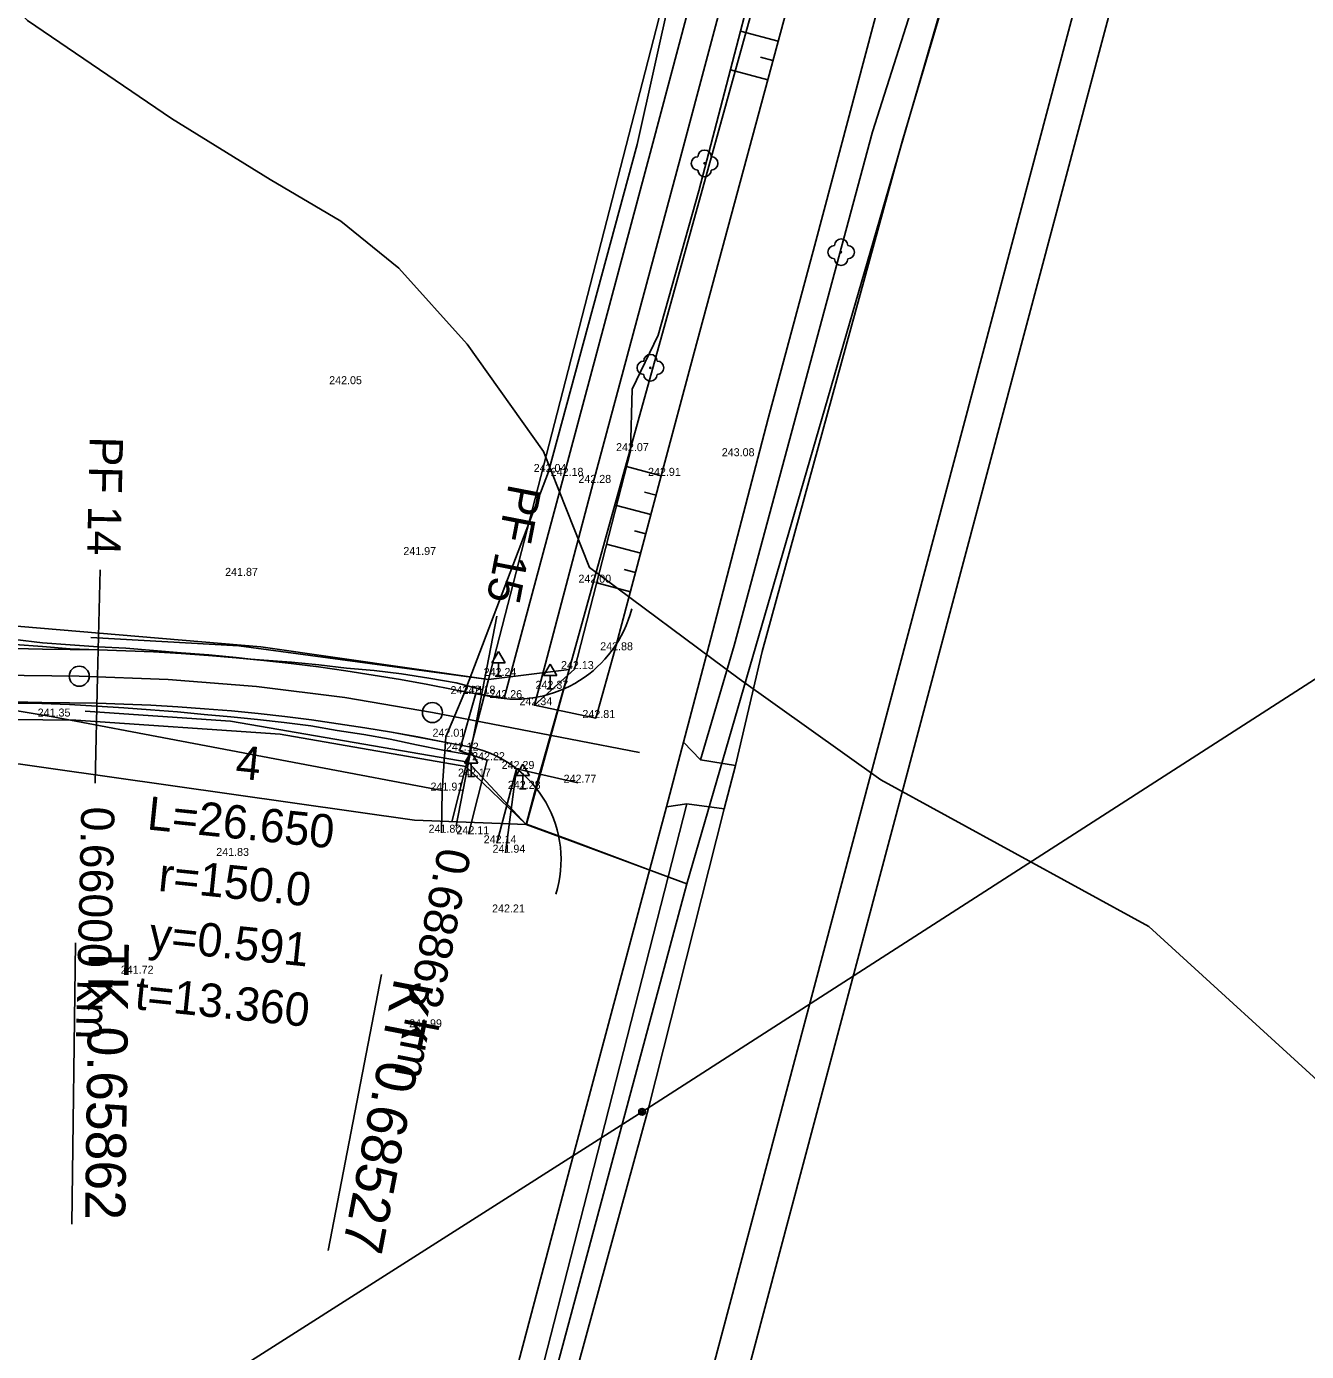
# Model space of a CAD drawing. Extents: x -555887 to -552101, y -1100251 to -1096546.
# Drawn here: x -554028.8 to -553932.8, y -1098461.3 to -1098361.9 of the extents above; entities that cross this region are included whole.
import ezdxf

# ---------------------------------------------------------------- set-up
doc = ezdxf.new("R2010")
doc.units = 0
for name, color, linetype in [('07_ELEKTRO', 7, 'Continuous'), ('07_KANALIZACE', 7, 'Continuous'), ('07_VODOVOD', 7, 'Continuous'), ('PARCELY_cesty', 7, 'Continuous'), ('PARCELY_silnice', 7, 'Continuous'), ('POLYGONY_rozšíření', 7, 'Continuous'), ('POLYGONY_SITUACE_PF', 7, 'Continuous'), ('POLYGONY_SITUACE_PF_POPISY', 7, 'Continuous'), ('POLYGONY_SITUACE_PO', 7, 'Continuous'), ('ROZHLED_parcela_cesty', 7, 'Continuous'), ('vrstevnice', 7, 'Continuous'), ('Výškopis', 7, 'Continuous'), ('ZSST', 7, 'Continuous'), ('zájem', 7, 'Continuous')]:
    doc.layers.add(name, color=color, linetype=linetype)

msp = doc.modelspace()

# ---------------------------------------------------------------- linework, layer by layer
for p, q in [((-554025.076, -1098430.632), (-554025.365, -1098451.722)), ((-554002.13, -1098432.993), (-554006.142, -1098453.7))]:
    msp.add_line(p, q)
at = {"layer": '07_ELEKTRO'}
msp.add_line((-554067.43, -1098497.29), (-553982.61, -1098443.29), dxfattribs=at)
msp.add_lwpolyline([(-553982.61, -1098443.29), (-553898.74, -1098389.37), (-553814.74, -1098335.79), (-553822.57, -1098304.65)], dxfattribs=at)
at = {"layer": '07_KANALIZACE'}
msp.add_lwpolyline([(-554087.209, -1098884.94), (-554044.091, -1098723.546), (-553946.28, -1098356.13), (-553945.28, -1098350.61), (-553945.106, -1098348.205), (-553937.04, -1098317.66), (-553932.95, -1098309.77), (-553933.89, -1098299.13), (-553960.89, -1098094.71)], dxfattribs=at)
at = {"layer": '07_VODOVOD'}
msp.add_lwpolyline([(-554079.661, -1098847.144), (-553997.696, -1098539.175), (-553945.85, -1098344.3), (-553938.248, -1098317.523), (-553935.78, -1098308.01), (-553936.175, -1098296.386), (-554003.21, -1097797.26)], dxfattribs=at)
at = {"layer": 'PARCELY_cesty'}
for points in [[(-554666.58, -1098424.3), (-554661.613, -1098426.35), (-554474.619, -1098365.555), (-554470.001, -1098364.247), (-554462.918, -1098362.998), (-554455.97, -1098362.75), (-554451.048, -1098362.623), (-554296.95, -1098373.16), (-554290.885, -1098371.599), (-554270.388, -1098373.304), (-554264.04, -1098376.17), (-554253.344, -1098377.565), (-554081.032, -1098403.398), (-554065.658, -1098405.306), (-554039.82, -1098406.01), (-554011.196, -1098408.42), (-553994.13, -1098410.89)], [(-553996.876, -1098421.543), (-553995.81, -1098417.41), (-553994.13, -1098410.89)], [(-554054.66, -1098413.62), (-554025.06, -1098413.92), (-554009.73, -1098414.99), (-553995.81, -1098417.41), (-553991.3, -1098421.75)]]:
    msp.add_lwpolyline(points, dxfattribs=at)
at = {"layer": 'PARCELY_silnice'}
for points in [[(-553977.83, -1098347.65), (-553971.09, -1098348.95), (-553988.06, -1098410.12), (-553994.13, -1098410.89)], [(-553988.06, -1098410.12), (-553991.282, -1098421.727), (-553987.992, -1098422.937), (-553982.15, -1098425.12), (-553979.24, -1098426.19), (-553957.61, -1098351.63), (-553971.09, -1098348.95)]]:
    msp.add_lwpolyline(points, close=True, dxfattribs=at)
at = {"layer": 'POLYGONY_rozšíření'}
for centre, radius, start, end in [((-553992.106, -1098403.347), 9.007, 259.0322, 345.60865), ((-553997.328, -1098424.393), 8.648, 342.61563, 77.16163)]:
    msp.add_arc(centre, radius, start, end, dxfattribs=at)
at = {"layer": 'POLYGONY_SITUACE_PF'}
for p, q in [((-554023.24, -1098402.661), (-554023.423, -1098410.659)), ((-553993.504, -1098406.144), (-553995.026, -1098413.998)), ((-554023.423, -1098410.659), (-554023.606, -1098418.657)), ((-553995.026, -1098413.998), (-553996.547, -1098421.852))]:
    msp.add_line(p, q, dxfattribs=at)
at = {"layer": 'POLYGONY_SITUACE_PO'}
for p, q in [((-554029.645, -1098408.567), (-554027.561, -1098408.595)), ((-554029.64, -1098408.25), (-554027.559, -1098408.414)), ((-554029.635, -1098407.883), (-554027.555, -1098408.122)), ((-554027.561, -1098408.595), (-554025.478, -1098408.624)), ((-554027.559, -1098408.414), (-554025.478, -1098408.578)), ((-554027.555, -1098408.122), (-554025.474, -1098408.274)), ((-554025.478, -1098408.578), (-554023.377, -1098408.659)), ((-554025.478, -1098408.624), (-554023.377, -1098408.659)), ((-554025.474, -1098408.274), (-554023.372, -1098408.436)), ((-554023.377, -1098408.659), (-554021.306, -1098408.727)), ((-554023.377, -1098408.659), (-554021.306, -1098408.727)), ((-554023.372, -1098408.436), (-554021.299, -1098408.537)), ((-554021.306, -1098408.727), (-554019.235, -1098408.813)), ((-554021.306, -1098408.727), (-554019.235, -1098408.813)), ((-554021.299, -1098408.537), (-554019.229, -1098408.699)), ((-554019.235, -1098408.813), (-554017.166, -1098408.929)), ((-554019.235, -1098408.813), (-554017.166, -1098408.929)), ((-554019.229, -1098408.699), (-554017.163, -1098408.884)), ((-554017.166, -1098408.929), (-554015.099, -1098409.082)), ((-554017.166, -1098408.929), (-554015.099, -1098409.082)), ((-554017.163, -1098408.884), (-554015.096, -1098409.039)), ((-554015.099, -1098409.082), (-554013.034, -1098409.252)), ((-554015.099, -1098409.082), (-554013.034, -1098409.252)), ((-554015.096, -1098409.039), (-554013.031, -1098409.219)), ((-554013.034, -1098409.252), (-554010.971, -1098409.457)), ((-554013.034, -1098409.252), (-554010.971, -1098409.457)), ((-554013.031, -1098409.219), (-554011.938, -1098409.361)), ((-554011.938, -1098409.361), (-554010.968, -1098409.428)), ((-554010.971, -1098409.457), (-554008.912, -1098409.686)), ((-554010.971, -1098409.457), (-554008.912, -1098409.686)), ((-554010.968, -1098409.428), (-554008.899, -1098409.582)), ((-554008.912, -1098409.686), (-554006.855, -1098409.94)), ((-554008.912, -1098409.686), (-554006.855, -1098409.94)), ((-554008.899, -1098409.582), (-554006.835, -1098409.791)), ((-554006.835, -1098409.791), (-554004.774, -1098410.034)), ((-554040.169, -1098410.423), (-554024.801, -1098410.634)), ((-554024.801, -1098410.634), (-554018.144, -1098410.873)), ((-554006.855, -1098409.94), (-554004.803, -1098410.235)), ((-554006.855, -1098409.94), (-554004.803, -1098410.235)), ((-554004.803, -1098410.235), (-554002.754, -1098410.546)), ((-554004.803, -1098410.235), (-554002.754, -1098410.546)), ((-554004.774, -1098410.034), (-554002.701, -1098410.216)), ((-554002.754, -1098410.546), (-554000.71, -1098410.883)), ((-554002.754, -1098410.546), (-554000.71, -1098410.883)), ((-554002.701, -1098410.216), (-554000.636, -1098410.46)), ((-554000.636, -1098410.46), (-553998.583, -1098410.792)), ((-553998.583, -1098410.792), (-553996.551, -1098411.119)), ((-554018.144, -1098410.873), (-554011.503, -1098411.407)), ((-554011.503, -1098411.407), (-554004.893, -1098412.236)), ((-554000.71, -1098410.883), (-553998.672, -1098411.26)), ((-554000.71, -1098410.883), (-553998.672, -1098411.26)), ((-553998.672, -1098411.26), (-553996.653, -1098411.645)), ((-553998.672, -1098411.26), (-553996.653, -1098411.645)), ((-553996.653, -1098411.645), (-553994.645, -1098412.034)), ((-553996.653, -1098411.645), (-553993.82, -1098412.19)), ((-553996.551, -1098411.119), (-553994.574, -1098411.665)), ((-554029.701, -1098412.649), (-554027.618, -1098412.68)), ((-554029.699, -1098412.567), (-554027.616, -1098412.595)), ((-554029.699, -1098412.567), (-554027.616, -1098412.595)), ((-554027.618, -1098412.68), (-554025.535, -1098412.751)), ((-554027.616, -1098412.595), (-554025.533, -1098412.624)), ((-554027.616, -1098412.595), (-554025.533, -1098412.624)), ((-554025.535, -1098412.751), (-554023.474, -1098412.878)), ((-554025.533, -1098412.624), (-554023.469, -1098412.658)), ((-554025.533, -1098412.624), (-554023.469, -1098412.658)), ((-554023.469, -1098412.658), (-554021.452, -1098412.724)), ((-554023.469, -1098412.658), (-554021.452, -1098412.724)), ((-554021.452, -1098412.724), (-554019.436, -1098412.808)), ((-554021.452, -1098412.724), (-554019.436, -1098412.808)), ((-554019.436, -1098412.808), (-554017.421, -1098412.921)), ((-554019.436, -1098412.808), (-554017.421, -1098412.921)), ((-554004.893, -1098412.236), (-553998.326, -1098413.358)), ((-554023.474, -1098412.878), (-554021.462, -1098413.003)), ((-554021.462, -1098413.003), (-554019.453, -1098413.16)), ((-554019.453, -1098413.16), (-554017.445, -1098413.302)), ((-554017.445, -1098413.302), (-554015.441, -1098413.494)), ((-554017.421, -1098412.921), (-554015.408, -1098413.07)), ((-554017.421, -1098412.921), (-554015.408, -1098413.07)), ((-554015.441, -1098413.494), (-554013.438, -1098413.676)), ((-554015.408, -1098413.07), (-554013.397, -1098413.235)), ((-554015.408, -1098413.07), (-554013.397, -1098413.235)), ((-554013.438, -1098413.676), (-554011.437, -1098413.885)), ((-554013.397, -1098413.235), (-554011.389, -1098413.435)), ((-554013.397, -1098413.235), (-554011.389, -1098413.435)), ((-554011.389, -1098413.435), (-554009.384, -1098413.658)), ((-554011.389, -1098413.435), (-554009.384, -1098413.658)), ((-554009.384, -1098413.658), (-554007.381, -1098413.905)), ((-554009.384, -1098413.658), (-554007.381, -1098413.905)), ((-553998.326, -1098413.358), (-553982.81, -1098416.364)), ((-554011.437, -1098413.885), (-554009.438, -1098414.111)), ((-554009.438, -1098414.111), (-554007.441, -1098414.354)), ((-554007.441, -1098414.354), (-554005.457, -1098414.695)), ((-554007.381, -1098413.905), (-554005.384, -1098414.193)), ((-554007.381, -1098413.905), (-554005.384, -1098414.193)), ((-554005.457, -1098414.695), (-554003.469, -1098414.998)), ((-554005.384, -1098414.193), (-554003.389, -1098414.495)), ((-554005.384, -1098414.193), (-554003.389, -1098414.495)), ((-554003.389, -1098414.495), (-554001.398, -1098414.824)), ((-554003.389, -1098414.495), (-554001.398, -1098414.824)), ((-554001.398, -1098414.824), (-553999.413, -1098415.19)), ((-554001.398, -1098414.824), (-553995.406, -1098415.962)), ((-554003.469, -1098414.998), (-554001.491, -1098415.36)), ((-554001.491, -1098415.36), (-553999.525, -1098415.783)), ((-553999.525, -1098415.783), (-553997.53, -1098416.17)), ((-553999.413, -1098415.19), (-553997.414, -1098415.572)), ((-553997.414, -1098415.572), (-553995.406, -1098415.961)), ((-553997.53, -1098416.17), (-553995.515, -1098416.521))]:
    msp.add_line(p, q, dxfattribs=at)
for centre in [(-554024.801, -1098410.634), (-553998.326, -1098413.358)]:
    msp.add_circle(centre, 0.75, dxfattribs=at)
at = {"layer": 'ROZHLED_parcela_cesty'}
msp.add_lwpolyline([(-554024.36, -1098413.26), (-554013.45, -1098414.01), (-553995.64, -1098417.08), (-553991.3, -1098421.75), (-553990.41, -1098418.43), (-553988.66, -1098412.24), (-553988.06, -1098410.12), (-553994.13, -1098410.89), (-554012.84, -1098408.35), (-554023.94, -1098407.74)], dxfattribs=at)
at = {"layer": 'vrstevnice'}
msp.add_lwpolyline([(-554031.026, -1098298.897), (-554035.452, -1098307.125), (-554039.309, -1098315.099), (-554043.291, -1098327.541), (-554043.87, -1098338.123), (-554041.542, -1098346.28), (-554037.622, -1098352.542), (-554028.673, -1098361.478), (-554017.894, -1098368.808), (-554010.495, -1098373.386), (-554005.187, -1098376.518), (-554000.845, -1098380.051), (-553995.729, -1098385.745), (-553989.99, -1098393.779), (-553986.558, -1098402.488), (-553975.316, -1098410.837), (-553964.711, -1098418.402), (-553944.61, -1098429.395), (-553930.532, -1098442.245)], dxfattribs=at)
at = {"layer": 'ZSST'}
for p, q in [((-553965.33, -1098369.81), (-553958.85, -1098349.53)), ((-553972.403, -1098363.022), (-553975.218, -1098362.264)), ((-553972.793, -1098364.47), (-553973.727, -1098364.219)), ((-553973.183, -1098365.919), (-553975.974, -1098365.167)), ((-553981.17, -1098395.61), (-553983.768, -1098394.921)), ((-553981.555, -1098397.06), (-553982.416, -1098396.831)), ((-553981.939, -1098398.51), (-553984.515, -1098397.826)), ((-553982.324, -1098399.96), (-553983.178, -1098399.733)), ((-553982.709, -1098401.409), (-553985.262, -1098400.732)), ((-553983.093, -1098402.859), (-553983.94, -1098402.635)), ((-553983.478, -1098404.309), (-553986.009, -1098403.638)), ((-553993.87, -1098409.62), (-553993.37, -1098408.77)), ((-553993.37, -1098408.77), (-553992.87, -1098409.62)), ((-553993.87, -1098409.62), (-553992.87, -1098409.62)), ((-553993.37, -1098410.62), (-553993.37, -1098409.62)), ((-553989.99, -1098410.58), (-553989.49, -1098409.73)), ((-553989.49, -1098409.73), (-553988.99, -1098410.58)), ((-553993.62, -1098410.62), (-553993.12, -1098410.62)), ((-553989.99, -1098410.58), (-553988.99, -1098410.58)), ((-553989.49, -1098411.58), (-553989.49, -1098410.58)), ((-553989.74, -1098411.58), (-553989.24, -1098411.58)), ((-553996.3, -1098416.22), (-553995.06, -1098411.94)), ((-553995.93, -1098417.16), (-553995.43, -1098416.31)), ((-553995.43, -1098416.31), (-553994.93, -1098417.16)), ((-553995.93, -1098417.16), (-553994.93, -1098417.16)), ((-553995.43, -1098418.16), (-553995.43, -1098417.16)), ((-553992.85, -1098423.87), (-553992.02, -1098417.59)), ((-553992.05, -1098418.08), (-553991.55, -1098417.23)), ((-553991.55, -1098417.23), (-553991.05, -1098418.08)), ((-553995.68, -1098418.16), (-553995.18, -1098418.16)), ((-553992.05, -1098418.08), (-553991.05, -1098418.08)), ((-553991.55, -1098419.08), (-553991.55, -1098418.08)), ((-553991.8, -1098419.08), (-553991.3, -1098419.08))]:
    msp.add_line(p, q, dxfattribs=at)
for points in [[(-553981.91, -1098371.05), (-553975.78, -1098348), (-553971.03, -1098329.61), (-553969.94, -1098324.32), (-553971.94, -1098323.51), (-553971.44, -1098318.93), (-553969.06, -1098318.21), (-553968.22, -1098303.02), (-553968.41, -1098291.14), (-553970.99, -1098268.85), (-553973.86, -1098246.72), (-553977.39, -1098220.02), (-553982.05, -1098183.91), (-553985.32, -1098159.26), (-553988.25, -1098137.18)], [(-553982.61, -1098443.29), (-553898.74, -1098389.37), (-553814.74, -1098335.79), (-553822.57, -1098304.65)], [(-553997.63, -1098422.37), (-553997.6, -1098419.21), (-554026.91, -1098413.66), (-554080.54, -1098404.72), (-554146.56, -1098393), (-554145.83, -1098373.42), (-554147.56, -1098338.87), (-554148.86, -1098314.99)], [(-554148.86, -1098314.99), (-554114.15, -1098321.64), (-554085.61, -1098327.06), (-554061.07, -1098330.97), (-554040.28, -1098335.39), (-554018.66, -1098339.2), (-553990.69, -1098343.82), (-553977.83, -1098347.63), (-553982.98, -1098370.76), (-553989.63, -1098395.32), (-553995.97, -1098411.98), (-553997.32, -1098415.17), (-553997.6, -1098419.21)], [(-553948.1, -1098341.33), (-553953.3, -1098345.41), (-553957.62, -1098352.08), (-553963.11, -1098370.53), (-553973.59, -1098408.79), (-553975.59, -1098417.34)], [(-554054.81, -1098696.59), (-554053.95, -1098693.56), (-554052.78, -1098689.01), (-554042.99, -1098652.55), (-554033.29, -1098616.71), (-554022.44, -1098576.81), (-554007.03, -1098518.73), (-553997.47, -1098483.19), (-553987.92, -1098447.16), (-553980.78, -1098420.44), (-553979.49, -1098415.59), (-553977.44, -1098407.81), (-553973.16, -1098391.31), (-553969.69, -1098378.4), (-553965.21, -1098361.58), (-553960.59, -1098344.24)], [(-553986.08, -1098413.77), (-553990.68, -1098412.81), (-553986.26, -1098396.14), (-553979.73, -1098371.75), (-553973.54, -1098348.54)], [(-553990.68, -1098412.81), (-553987.67, -1098410.1), (-553983.47, -1098393.76), (-553983.35, -1098389.1), (-553981.39, -1098385.06), (-553978.34, -1098374.25), (-553971.82, -1098349.22)], [(-553970.63, -1098356.44), (-553978.69, -1098386.36), (-553981.17, -1098395.61), (-553984.64, -1098408.69), (-553986.08, -1098413.77)], [(-553978.22, -1098416.9), (-553975.7, -1098408.34), (-553965.33, -1098369.81)], [(-553981.91, -1098371.05), (-553988.46, -1098395.61), (-553992.94, -1098412.28), (-553995.06, -1098411.94)], [(-553979.49, -1098415.59), (-553978.22, -1098416.9), (-553975.59, -1098417.34), (-553976.46, -1098420.59), (-553979.26, -1098420.2), (-553980.78, -1098420.44)], [(-553996.3, -1098416.22), (-553994.21, -1098416.93), (-553995.63, -1098422.48)], [(-553993.49, -1098423.16), (-553992.02, -1098417.59), (-553987.42, -1098418.62)], [(-554049.19, -1098691), (-554050.52, -1098687.46), (-554041.41, -1098653.36), (-554031.87, -1098617.14), (-554021.28, -1098577.24), (-554005.55, -1098519.29), (-553995.62, -1098484.1), (-553986.23, -1098447.46), (-553979.26, -1098420.2)], [(-553976.46, -1098420.59), (-553982.14, -1098443.13), (-553993.59, -1098484.91), (-554003.65, -1098520), (-554019.29, -1098577.95), (-554030.05, -1098617.61), (-554040, -1098653.89), (-554048.29, -1098689.04)]]:
    msp.add_lwpolyline(points, dxfattribs=at)
for centre, radius in [((-553977.92, -1098372.18), 0.05), ((-553967.68, -1098378.84), 0.05), ((-553981.98, -1098387.51), 0.05), ((-553982.61, -1098443.29), 0.25), ((-553982.61, -1098443.29), 0.158), ((-553982.61, -1098443.29), 0.05)]:
    msp.add_circle(centre, radius, dxfattribs=at)
for centre, start, end in [((-553978.42, -1098372.18), 90, 270), ((-553977.92, -1098371.68), 0, 180), ((-553977.42, -1098372.18), 270, 90), ((-553977.92, -1098372.68), 180, 0), ((-553967.68, -1098378.34), 0, 180), ((-553968.18, -1098378.84), 90, 270), ((-553967.18, -1098378.84), 270, 90), ((-553967.68, -1098379.34), 180, 0), ((-553982.48, -1098387.51), 90, 270), ((-553981.98, -1098387.01), 0, 180), ((-553981.48, -1098387.51), 270, 90), ((-553981.98, -1098388.01), 180, 0)]:
    msp.add_arc(centre, 0.5, start, end, dxfattribs=at)
at = {"layer": 'zájem'}
for points in [[(-554271.92, -1098380.9), (-554131.79, -1098402.65), (-553999.67, -1098421.44), (-553991.3, -1098421.75), (-553988.01, -1098422.96), (-553982.15, -1098425.12), (-553979.24, -1098426.19), (-554050.69, -1098691.93)], [(-554050.69, -1098691.93), (-553979.24, -1098426.19), (-553982.15, -1098425.12), (-553988.01, -1098422.96), (-553991.3, -1098421.75), (-553999.67, -1098421.44), (-554131.79, -1098402.65), (-554271.92, -1098380.9)]]:
    msp.add_lwpolyline(points, dxfattribs=at)

# ---------------------------------------------------------------- texts
for s, height, rotation, p in [('4', 2.5, 354.12426, (-554013.157, -1098418.274)), ('L=26.650', 2.5, 354.12426, (-554019.777, -1098422.117)), ('r=150.0', 2.5, 354.12426, (-554018.937, -1098426.727)), ('y=0.591', 2.5, 354.12426, (-554019.647, -1098431.178)), ('TK 0.65862', 3, 269.21411, (-554024.076, -1098430.645)), ('t=13.360', 2.5, 354.12426, (-554020.7, -1098435.593)), ('KT 0.68527', 3, 259.03441, (-554001.148, -1098433.183))]:
    msp.add_text(s, height=height, rotation=rotation).set_placement(p)
at = {"layer": 'POLYGONY_SITUACE_PF_POPISY'}
for s, rotation, p in [('PF 14', 268.68747, (-554024.01, -1098392.641)), ('PF 15', 259.03441, (-553992.583, -1098396.136)), ('0.66000 km', 268.68747, (-554024.646, -1098420.386)), ('0.68863 km', 259.03441, (-553997.863, -1098423.382))]:
    msp.add_text(s, height=2.5, rotation=rotation, dxfattribs=at).set_placement(p)
at = {"layer": 'Výškopis'}
for s, p in [('242.05', (-554006.062, -1098388.74)), ('242.07', (-553984.556, -1098393.76)), ('243.08', (-553976.628, -1098394.14)), ('242.04', (-553990.728, -1098395.32)), ('242.18', (-553989.454, -1098395.61)), ('242.28', (-553987.378, -1098396.14)), ('242.91', (-553982.158, -1098395.61)), ('241.97', (-554000.505, -1098401.55)), ('241.87', (-554013.862, -1098403.11)), ('242.00', (-553987.376, -1098403.62)), ('242.88', (-553985.744, -1098408.69)), ('242.13', (-553988.684, -1098410.1)), ('242.24', (-553994.482, -1098410.62)), ('242.01', (-553996.966, -1098411.98)), ('242.18', (-553996.054, -1098411.94)), ('242.26', (-553994.052, -1098412.28)), ('242.37', (-553990.594, -1098411.58)), ('242.34', (-553991.796, -1098412.81)), ('241.35', (-554027.916, -1098413.66)), ('242.81', (-553987.076, -1098413.77)), ('242.01', (-553998.316, -1098415.17)), ('242.12', (-553997.31, -1098416.22)), ('242.22', (-553995.344, -1098416.93)), ('242.17', (-553996.406, -1098418.16)), ('242.29', (-553993.132, -1098417.59)), ('241.91', (-553998.464, -1098419.21)), ('242.28', (-553992.668, -1098419.08)), ('242.77', (-553988.487, -1098418.62)), ('241.80', (-553998.612, -1098422.37)), ('242.11', (-553996.516, -1098422.48)), ('242.14', (-553994.478, -1098423.16)), ('241.83', (-554014.53, -1098424.11)), ('241.94', (-553993.816, -1098423.87)), ('242.21', (-553993.85, -1098428.35)), ('241.72', (-554021.686, -1098432.94)), ('241.99', (-554000.066, -1098436.96))]:
    msp.add_text(s, height=0.6, dxfattribs=at).set_placement(p)

doc.saveas('drawing.dxf')
